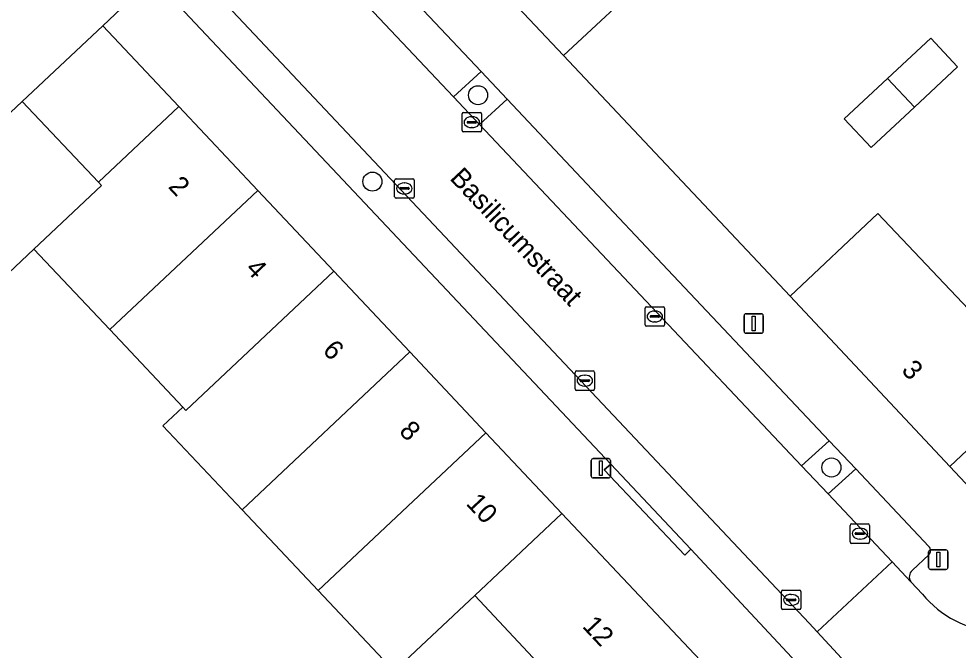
# Model space of a CAD drawing. Extents: x 162542 to 163147, y 380779 to 381521.
# Drawn here: x 162623.92 to 162672.17, y 381250.74 to 381283.2 of the extents above; entities that cross this region are included whole.
import ezdxf

# ---------------------------------------------------------------- set-up
doc = ezdxf.new("R2010")
doc.units = 0
for name, color, linetype in [('IMGEO_Boom', 7, 'Continuous'), ('IMGEO_Erf', 7, 'Continuous'), ('IMGEO_Groenvoorziening', 7, 'Continuous'), ('IMGEO_Kolk', 7, 'Continuous'), ('IMGEO_Lichtmast', 7, 'Continuous'), ('IMGEO_Muur', 7, 'Continuous'), ('IMGEO_Openbare_ruimte_label', 7, 'Continuous'), ('IMGEO_Pand', 7, 'Continuous'), ('IMGEO_Pand_nummerreeks', 7, 'Continuous'), ('IMGEO_Parkeervlak_open', 7, 'Continuous'), ('IMGEO_Rijbaan_lokaal_open', 7, 'Continuous'), ('IMGEO_Voetpad_open', 7, 'Continuous')]:
    doc.layers.add(name, color=color, linetype=linetype)

msp = doc.modelspace()

# ---------------------------------------------------------------- linework, layer by layer
at = {"layer": 'IMGEO_Boom'}
for centre in [(162647.508, 381279.271), (162642.083, 381274.829), (162665.662, 381260.133)]:
    msp.add_circle(centre, 0.489, dxfattribs=at)
at = {"layer": 'IMGEO_Erf'}
for points in [[(162656.442, 381285.541), (162651.893, 381281.31), (162663.55, 381268.948), (162668.042, 381273.197), (162673.01, 381267.944), (162676.738, 381271.471), (162680.467, 381274.998), (162678.406, 381277.177), (162682.72, 381281.239), (162686.65, 381284.939)], [(162621.963, 381246.057), (162623.94, 381247.911), (162625.924, 381249.772), (162626.129, 381249.553), (162626.937, 381250.31), (162639.885, 381236.552), (162644.204, 381240.617), (162648.355, 381244.524), (162652.309, 381248.246), (162647.338, 381253.552), (162643.203, 381249.659), (162639.294, 381253.809), (162635.386, 381257.959), (162631.32, 381262.277), (162632.34, 381263.237), (162628.589, 381267.219), (162624.695, 381271.355), (162619.859, 381266.803)]]:
    msp.add_lwpolyline(points, dxfattribs=at)
for points in [[(162628.238, 381282.845), (162624.093, 381278.942), (162628.006, 381274.809), (162632.139, 381278.693)], [(162668.537, 381280.135), (162670.76, 381282.21), (162672.146, 381280.729), (162669.922, 381278.652), (162667.697, 381276.576), (162666.312, 381278.058)], [(162675.897, 381264.11), (162671.751, 381260.191), (162675.45, 381256.242), (162679.611, 381260.161)]]:
    msp.add_lwpolyline(points, close=True, dxfattribs=at)
at = {"layer": 'IMGEO_Groenvoorziening'}
for points in [[(162649.002, 381279.066), (162647.665, 381280.485), (162646.243, 381279.193), (162647.584, 381277.771)], [(162665.547, 381261.505), (162664.121, 381260.226), (162665.49, 381258.773), (162666.912, 381260.058)]]:
    msp.add_lwpolyline(points, close=True, dxfattribs=at)
at = {"layer": 'IMGEO_Kolk'}
for p, q in [((162646.688, 381277.459), (162646.688, 381278.311)), ((162646.763, 381278.385), (162647.615, 381278.385)), ((162647.176, 381278.165), (162647.201, 381278.165)), ((162647.689, 381278.311), (162647.689, 381277.459)), ((162646.947, 381277.879), (162646.947, 381277.891)), ((162647.385, 381277.842), (162646.987, 381277.842)), ((162646.99, 381277.928), (162647.388, 381277.928)), ((162647.199, 381277.605), (162647.174, 381277.605)), ((162647.431, 381277.891), (162647.431, 381277.879)), ((162647.615, 381277.385), (162646.763, 381277.385)), ((162643.226, 381274.053), (162643.226, 381274.905)), ((162643.301, 381274.979), (162644.153, 381274.979)), ((162643.714, 381274.759), (162643.739, 381274.759)), ((162644.227, 381274.905), (162644.227, 381274.053)), ((162643.485, 381274.473), (162643.485, 381274.485)), ((162643.923, 381274.436), (162643.525, 381274.436)), ((162643.528, 381274.522), (162643.926, 381274.522)), ((162643.737, 381274.199), (162643.712, 381274.199)), ((162643.969, 381274.485), (162643.969, 381274.473)), ((162644.153, 381273.979), (162643.301, 381273.979)), ((162656.089, 381267.47), (162656.089, 381268.322)), ((162656.164, 381268.396), (162657.016, 381268.396)), ((162656.391, 381267.939), (162656.789, 381267.939)), ((162656.577, 381268.176), (162656.602, 381268.176)), ((162657.09, 381268.322), (162657.09, 381267.47)), ((162656.348, 381267.89), (162656.348, 381267.902)), ((162656.786, 381267.853), (162656.388, 381267.853)), ((162656.6, 381267.616), (162656.575, 381267.616)), ((162656.832, 381267.902), (162656.832, 381267.89)), ((162657.016, 381267.396), (162656.164, 381267.396)), ((162652.57, 381265.099), (162653.422, 381265.099)), ((162652.495, 381264.173), (162652.495, 381265.025)), ((162652.754, 381264.593), (162652.754, 381264.605)), ((162653.192, 381264.556), (162652.794, 381264.556)), ((162652.797, 381264.642), (162653.195, 381264.642)), ((162652.983, 381264.879), (162653.008, 381264.879)), ((162653.238, 381264.605), (162653.238, 381264.593)), ((162653.496, 381265.025), (162653.496, 381264.173)), ((162653.422, 381264.099), (162652.57, 381264.099)), ((162653.006, 381264.319), (162652.981, 381264.319)), ((162666.624, 381256.308), (162666.624, 381257.16)), ((162666.699, 381257.234), (162667.551, 381257.234)), ((162667.112, 381257.014), (162667.137, 381257.014)), ((162667.625, 381257.16), (162667.625, 381256.308)), ((162666.883, 381256.728), (162666.883, 381256.74)), ((162667.321, 381256.691), (162666.923, 381256.691)), ((162666.926, 381256.777), (162667.324, 381256.777)), ((162667.135, 381256.454), (162667.11, 381256.454)), ((162667.367, 381256.74), (162667.367, 381256.728)), ((162667.551, 381256.234), (162666.699, 381256.234)), ((162663.096, 381252.9), (162663.096, 381253.752)), ((162663.171, 381253.826), (162664.023, 381253.826)), ((162663.584, 381253.606), (162663.609, 381253.606)), ((162664.097, 381253.752), (162664.097, 381252.9)), ((162663.355, 381253.32), (162663.355, 381253.332)), ((162663.793, 381253.283), (162663.395, 381253.283)), ((162663.398, 381253.369), (162663.796, 381253.369)), ((162663.607, 381253.046), (162663.582, 381253.046)), ((162663.839, 381253.332), (162663.839, 381253.32)), ((162664.023, 381252.826), (162663.171, 381252.826))]:
    msp.add_line(p, q, dxfattribs=at)
for points in [[(162646.688, 381277.459), (162646.688, 381278.311)], [(162646.763, 381278.385), (162647.615, 381278.385)], [(162647.689, 381278.311), (162647.689, 381277.459)], [(162647.615, 381277.385), (162646.763, 381277.385)], [(162643.226, 381274.053), (162643.226, 381274.905)], [(162643.301, 381274.979), (162644.153, 381274.979)], [(162644.227, 381274.905), (162644.227, 381274.053)], [(162644.153, 381273.979), (162643.301, 381273.979)], [(162656.089, 381267.47), (162656.089, 381268.322)], [(162656.164, 381268.396), (162657.016, 381268.396)], [(162657.09, 381268.322), (162657.09, 381267.47)], [(162657.016, 381267.396), (162656.164, 381267.396)], [(162652.57, 381265.099), (162653.422, 381265.099)], [(162652.495, 381264.173), (162652.495, 381265.025)], [(162653.496, 381265.025), (162653.496, 381264.173)], [(162653.422, 381264.099), (162652.57, 381264.099)], [(162666.624, 381256.308), (162666.624, 381257.16)], [(162666.699, 381257.234), (162667.551, 381257.234)], [(162667.625, 381257.16), (162667.625, 381256.308)], [(162667.551, 381256.234), (162666.699, 381256.234)], [(162663.096, 381252.9), (162663.096, 381253.752)], [(162663.171, 381253.826), (162664.023, 381253.826)], [(162664.097, 381253.752), (162664.097, 381252.9)], [(162664.023, 381252.826), (162663.171, 381252.826)]]:
    msp.add_lwpolyline(points, dxfattribs=at)
for centre, radius, start, end in [((162646.765, 381278.309), 0.0765, 91.552, 178.448), ((162646.765, 381278.309), 0.0765, 91.552, 178.448), ((162647.613, 381278.309), 0.0765, 1.552, 88.448), ((162647.613, 381278.309), 0.0765, 1.552, 88.448), ((162646.987, 381277.888), 0.0403, 85.8775, 175.7526), ((162646.984, 381277.878), 0.0366, 178.938, 274.7102), ((162647.388, 381277.885), 0.043, 264.8664, 352.4533), ((162647.392, 381277.89), 0.0386, 1.7309, 96.639), ((162646.765, 381277.461), 0.0765, 181.552, 268.448), ((162646.765, 381277.461), 0.0765, 181.552, 268.448), ((162647.613, 381277.461), 0.0765, 271.552, 358.448), ((162647.613, 381277.461), 0.0765, 271.552, 358.448), ((162643.303, 381274.903), 0.0765, 91.552, 178.448), ((162643.303, 381274.903), 0.0765, 91.552, 178.448), ((162644.151, 381274.903), 0.0765, 1.552, 88.448), ((162644.151, 381274.903), 0.0765, 1.552, 88.448), ((162643.525, 381274.482), 0.0403, 85.8775, 175.7526), ((162643.522, 381274.472), 0.0366, 178.938, 274.7102), ((162643.926, 381274.479), 0.043, 264.8664, 352.4533), ((162643.93, 381274.484), 0.0386, 1.7309, 96.639), ((162643.303, 381274.055), 0.0765, 181.552, 268.448), ((162643.303, 381274.055), 0.0765, 181.552, 268.448), ((162644.151, 381274.055), 0.0765, 271.552, 358.448), ((162644.151, 381274.055), 0.0765, 271.552, 358.448), ((162656.166, 381268.32), 0.0765, 91.552, 178.448), ((162656.166, 381268.32), 0.0765, 91.552, 178.448), ((162656.388, 381267.899), 0.0403, 85.8775, 175.7526), ((162656.793, 381267.901), 0.0386, 1.7309, 96.639), ((162657.014, 381268.32), 0.0765, 1.552, 88.448), ((162657.014, 381268.32), 0.0765, 1.552, 88.448), ((162656.166, 381267.472), 0.0765, 181.552, 268.448), ((162656.166, 381267.472), 0.0765, 181.552, 268.448), ((162656.385, 381267.889), 0.0366, 178.938, 274.7102), ((162656.789, 381267.896), 0.043, 264.8664, 352.4533), ((162657.014, 381267.472), 0.0765, 271.552, 358.448), ((162657.014, 381267.472), 0.0765, 271.552, 358.448), ((162652.572, 381265.023), 0.0765, 91.552, 178.448), ((162652.572, 381265.023), 0.0765, 91.552, 178.448), ((162653.42, 381265.023), 0.0765, 1.552, 88.448), ((162653.42, 381265.023), 0.0765, 1.552, 88.448), ((162652.794, 381264.602), 0.0403, 85.8775, 175.7526), ((162652.791, 381264.592), 0.0366, 178.938, 274.7102), ((162653.195, 381264.599), 0.043, 264.8664, 352.4533), ((162653.199, 381264.604), 0.0386, 1.7309, 96.639), ((162652.572, 381264.175), 0.0765, 181.552, 268.448), ((162652.572, 381264.175), 0.0765, 181.552, 268.448), ((162653.42, 381264.175), 0.0765, 271.552, 358.448), ((162653.42, 381264.175), 0.0765, 271.552, 358.448), ((162666.701, 381257.158), 0.0765, 91.552, 178.448), ((162666.701, 381257.158), 0.0765, 91.552, 178.448), ((162667.549, 381257.158), 0.0765, 1.552, 88.448), ((162667.549, 381257.158), 0.0765, 1.552, 88.448), ((162666.923, 381256.737), 0.0403, 85.8775, 175.7526), ((162666.92, 381256.727), 0.0366, 178.938, 274.7102), ((162667.324, 381256.734), 0.043, 264.8664, 352.4533), ((162667.328, 381256.739), 0.0386, 1.7309, 96.639), ((162666.701, 381256.31), 0.0765, 181.552, 268.448), ((162666.701, 381256.31), 0.0765, 181.552, 268.448), ((162667.549, 381256.31), 0.0765, 271.552, 358.448), ((162667.549, 381256.31), 0.0765, 271.552, 358.448), ((162663.173, 381253.75), 0.0765, 91.552, 178.448), ((162663.173, 381253.75), 0.0765, 91.552, 178.448), ((162664.021, 381253.75), 0.0765, 1.552, 88.448), ((162664.021, 381253.75), 0.0765, 1.552, 88.448), ((162663.395, 381253.329), 0.0403, 85.8775, 175.7526), ((162663.392, 381253.319), 0.0366, 178.938, 274.7102), ((162663.796, 381253.326), 0.043, 264.8664, 352.4533), ((162663.8, 381253.331), 0.0386, 1.7309, 96.639), ((162663.173, 381252.902), 0.0765, 181.552, 268.448), ((162663.173, 381252.902), 0.0765, 181.552, 268.448), ((162664.021, 381252.902), 0.0765, 271.552, 358.448), ((162664.021, 381252.902), 0.0765, 271.552, 358.448)]:
    msp.add_arc(centre, radius, start, end, dxfattribs=at)
for centre, major_axis, ratio, start_param, end_param in [((162647.175, 381277.885), (-0.387, 0.002), 0.722429, 4.712389, 7.853982), ((162647.2, 381277.885), (-0.39, 0.002), 0.717154, 1.570796, 4.712389), ((162643.713, 381274.479), (-0.387, 0.002), 0.722429, 4.712389, 7.853982), ((162643.738, 381274.479), (-0.39, 0.002), 0.717154, 1.570796, 4.712389), ((162656.576, 381267.896), (-0.387, 0.002), 0.722429, 4.712389, 7.853982), ((162656.601, 381267.896), (-0.39, 0.002), 0.717154, 1.570796, 4.712389), ((162652.982, 381264.599), (-0.387, 0.002), 0.722429, 4.712389, 7.853982), ((162653.007, 381264.599), (-0.39, 0.002), 0.717154, 1.570796, 4.712389), ((162667.111, 381256.734), (-0.387, 0.002), 0.722429, 4.712389, 7.853982), ((162667.136, 381256.734), (-0.39, 0.002), 0.717154, 1.570796, 4.712389), ((162663.583, 381253.326), (-0.387, 0.002), 0.722429, 4.712389, 7.853982), ((162663.608, 381253.326), (-0.39, 0.002), 0.717154, 1.570796, 4.712389)]:
    msp.add_ellipse(centre, major_axis=major_axis, ratio=ratio, start_param=start_param, end_param=end_param, dxfattribs=at)
at = {"layer": 'IMGEO_Lichtmast'}
for p, q in [((162661.172, 381267.136), (162661.172, 381267.936)), ((162661.172, 381267.936), (162661.172, 381267.136)), ((162661.272, 381268.036), (162662.062, 381268.036)), ((162662.062, 381268.036), (162661.272, 381268.036)), ((162662.162, 381267.936), (162662.162, 381267.136)), ((162662.162, 381267.136), (162662.162, 381267.936)), ((162662.062, 381267.036), (162661.272, 381267.036)), ((162661.272, 381267.036), (162662.062, 381267.036)), ((162653.321, 381259.695), (162653.321, 381260.495)), ((162653.321, 381260.495), (162653.321, 381259.695)), ((162653.421, 381260.595), (162654.211, 381260.595)), ((162654.211, 381260.595), (162653.421, 381260.595)), ((162654.311, 381260.495), (162654.311, 381259.695)), ((162654.311, 381259.695), (162654.311, 381260.495)), ((162654.211, 381259.595), (162653.421, 381259.595)), ((162653.421, 381259.595), (162654.211, 381259.595)), ((162670.753, 381255.898), (162671.543, 381255.898)), ((162671.543, 381255.898), (162670.753, 381255.898)), ((162670.653, 381254.998), (162670.653, 381255.798)), ((162670.653, 381255.798), (162670.653, 381254.998)), ((162671.643, 381255.798), (162671.643, 381254.998)), ((162671.643, 381254.998), (162671.643, 381255.798)), ((162671.543, 381254.898), (162670.753, 381254.898)), ((162670.753, 381254.898), (162671.543, 381254.898))]:
    msp.add_line(p, q, dxfattribs=at)
for points in [[(162661.592, 381267.911), (162661.742, 381267.911), (162661.742, 381267.161), (162661.592, 381267.161), (162661.592, 381267.911)], [(162653.741, 381260.47), (162653.891, 381260.47), (162653.891, 381259.72), (162653.741, 381259.72), (162653.741, 381260.47)], [(162671.073, 381255.773), (162671.223, 381255.773), (162671.223, 381255.023), (162671.073, 381255.023), (162671.073, 381255.773)]]:
    msp.add_lwpolyline(points, dxfattribs=at)
for centre, start, end in [((162661.272, 381267.936), 90, 180), ((162661.272, 381267.936), 90, 180), ((162662.062, 381267.936), 0, 90), ((162662.062, 381267.936), 360, 90), ((162661.272, 381267.136), 180, 270), ((162661.272, 381267.136), 180, 270), ((162662.062, 381267.136), 270, 0), ((162662.062, 381267.136), 270, 0), ((162653.421, 381260.495), 90, 180), ((162653.421, 381260.495), 90, 180), ((162654.211, 381260.495), 0, 90), ((162654.211, 381260.495), 360, 90), ((162653.421, 381259.695), 180, 270), ((162653.421, 381259.695), 180, 270), ((162654.211, 381259.695), 270, 0), ((162654.211, 381259.695), 270, 0), ((162670.753, 381255.798), 90, 180), ((162670.753, 381255.798), 90, 180), ((162671.543, 381255.798), 0, 90), ((162671.543, 381255.798), 360, 90), ((162670.753, 381254.998), 180, 270), ((162670.753, 381254.998), 180, 270), ((162671.543, 381254.998), 270, 0), ((162671.543, 381254.998), 270, 0)]:
    msp.add_arc(centre, 0.1, start, end, dxfattribs=at)
at = {"layer": 'IMGEO_Muur'}
for points in [[(162624.093, 381278.942), (162628.238, 381282.845)], [(162628.238, 381282.845), (162632.139, 381278.693)]]:
    msp.add_lwpolyline(points, dxfattribs=at)
at = {"layer": 'IMGEO_Pand'}
for points in [[(162651.525, 381290.827), (162651.133, 381290.458), (162647.835, 381293.935), (162643.678, 381290.028), (162651.893, 381281.31), (162656.442, 381285.541)], [(162672.146, 381280.729), (162670.76, 381282.21), (162668.537, 381280.135), (162669.922, 381278.652)], [(162669.922, 381278.652), (162668.537, 381280.135), (162666.312, 381278.058), (162667.697, 381276.576)], [(162615.787, 381271.127), (162619.859, 381266.803), (162624.695, 381271.355), (162628.175, 381274.63), (162628.006, 381274.809), (162624.093, 381278.942)], [(162624.695, 381271.355), (162628.589, 381267.219), (162636.196, 381274.379), (162632.139, 381278.693), (162628.006, 381274.809), (162628.175, 381274.63)], [(162632.34, 381263.237), (162632.498, 381263.069), (162640.101, 381270.226), (162636.196, 381274.379), (162628.589, 381267.219)], [(162672.63, 381267.584), (162673.01, 381267.944), (162668.042, 381273.197), (162663.55, 381268.948), (162671.751, 381260.191), (162675.897, 381264.11)], [(162632.34, 381263.237), (162631.32, 381262.277), (162635.386, 381257.959), (162644.007, 381266.073), (162640.101, 381270.226), (162632.498, 381263.069)], [(162635.386, 381257.959), (162639.294, 381253.809), (162647.912, 381261.921), (162644.007, 381266.073)], [(162651.817, 381257.768), (162647.912, 381261.921), (162639.294, 381253.809), (162643.203, 381249.659), (162647.338, 381253.552)], [(162651.817, 381257.768), (162647.338, 381253.552), (162652.309, 381248.246), (162652.546, 381248.469), (162655.53, 381245.3), (162655.64, 381245.404), (162659.768, 381249.313)]]:
    msp.add_lwpolyline(points, close=True, dxfattribs=at)
at = {"layer": 'IMGEO_Parkeervlak_open'}
for points in [[(162638.045, 381287.891), (162646.243, 381279.193), (162647.665, 381280.485), (162639.66, 381288.983)], [(162666.912, 381260.058), (162665.49, 381258.773), (162668.779, 381255.283), (162669.741, 381254.263)], [(162670.664, 381256.08), (162666.912, 381260.058)], [(162669.819, 381254.852), (162670.67, 381255.641)]]:
    msp.add_lwpolyline(points, dxfattribs=at)
for points in [[(162633.777, 381284.795), (162633.421, 381285.165), (162632.137, 381283.873), (162654.323, 381260.31), (162658.435, 381255.931), (162664.817, 381249.106), (162666.184, 381250.338), (162664.93, 381251.684), (162664.513, 381252.131)], [(162649.002, 381279.066), (162647.584, 381277.771), (162664.121, 381260.226), (162665.547, 381261.505), (162657.257, 381270.294), (162653.1, 381274.715)]]:
    msp.add_lwpolyline(points, close=True, dxfattribs=at)
for centre, radius, start, end in [((162670.448, 381255.858), 0.31, 315.7199, 45.8462), ((162670.097, 381254.515), 0.437, 129.6014, 215.3113)]:
    msp.add_arc(centre, radius, start, end, dxfattribs=at)
at = {"layer": 'IMGEO_Rijbaan_lokaal_open'}
msp.add_lwpolyline([(162647.584, 381277.771), (162646.243, 381279.193), (162638.045, 381287.891), (162637.309, 381288.643), (162637.2, 381288.757), (162633.377, 381285.21), (162633.421, 381285.165), (162633.777, 381284.795), (162664.513, 381252.131), (162664.93, 381251.684), (162668.779, 381255.283), (162665.49, 381258.773), (162664.121, 381260.226)], close=True, dxfattribs=at)
msp.add_lwpolyline([(162670.335, 381253.63), (162669.741, 381254.263), (162668.779, 381255.283), (162664.93, 381251.684), (162666.184, 381250.338)], dxfattribs=at)
msp.add_arc((162674.457, 381256.971), 5.306, 219.0297, 313.1302, dxfattribs=at)
at = {"layer": 'IMGEO_Voetpad_open'}
for points in [[(162651.893, 381281.31), (162643.678, 381290.028), (162639.968, 381293.965), (162636, 381290.223)], [(162639.66, 381288.983), (162647.665, 381280.485), (162649.002, 381279.066), (162653.1, 381274.715), (162657.257, 381270.294), (162665.547, 381261.505), (162666.912, 381260.058), (162670.664, 381256.08)], [(162611.337, 381266.938), (162615.787, 381271.127), (162624.093, 381278.942), (162628.238, 381282.845), (162632.039, 381286.458)], [(162632.039, 381286.458), (162628.238, 381282.845), (162632.139, 381278.693), (162636.196, 381274.379), (162640.101, 381270.226), (162644.007, 381266.073), (162647.912, 381261.921), (162651.817, 381257.768), (162659.768, 381249.313), (162663.665, 381245.159), (162667.274, 381248.499)], [(162666.184, 381250.338), (162664.817, 381249.106), (162658.435, 381255.931), (162658.138, 381255.619), (162653.988, 381260.007), (162654.323, 381260.31), (162632.137, 381283.873)], [(162678.084, 381253.099), (162678.398, 381253.413), (162677.312, 381254.517), (162677.311, 381254.516), (162675.45, 381256.242), (162671.751, 381260.191), (162663.55, 381268.948), (162651.893, 381281.31)], [(162670.67, 381255.641), (162669.819, 381254.852)], [(162669.741, 381254.263), (162670.335, 381253.63)]]:
    msp.add_lwpolyline(points, dxfattribs=at)
msp.add_lwpolyline([(162658.435, 381255.931), (162654.323, 381260.31), (162653.988, 381260.007), (162658.138, 381255.619)], close=True, dxfattribs=at)
for centre, radius, start, end in [((162670.448, 381255.858), 0.31, 315.7199, 45.8462), ((162670.097, 381254.515), 0.437, 129.6014, 215.3113), ((162674.457, 381256.971), 5.306, 219.0297, 313.1302)]:
    msp.add_arc(centre, radius, start, end, dxfattribs=at)

# ---------------------------------------------------------------- texts
at = {"layer": 'IMGEO_Openbare_ruimte_label'}
msp.add_text('Basilicumstraat', height=1, rotation=313.2569, dxfattribs=at).set_placement((162646.014, 381274.969))
at = {"layer": 'IMGEO_Pand_nummerreeks'}
for s, rotation, p in [('2', 313.0983, (162631.55, 381274.543)), ('4', 313.3437, (162635.513, 381270.303)), ('6', 313.9972, (162639.476, 381266.108)), ('3', 312.9258, (162669.214, 381265.097)), ('8', 313.6973, (162643.408, 381261.956)), ('10', 312.9466, (162646.851, 381258.252)), ('12', 313.2355, (162652.82, 381251.945))]:
    msp.add_text(s, height=1, rotation=rotation, dxfattribs=at).set_placement(p)

doc.saveas('drawing.dxf')
